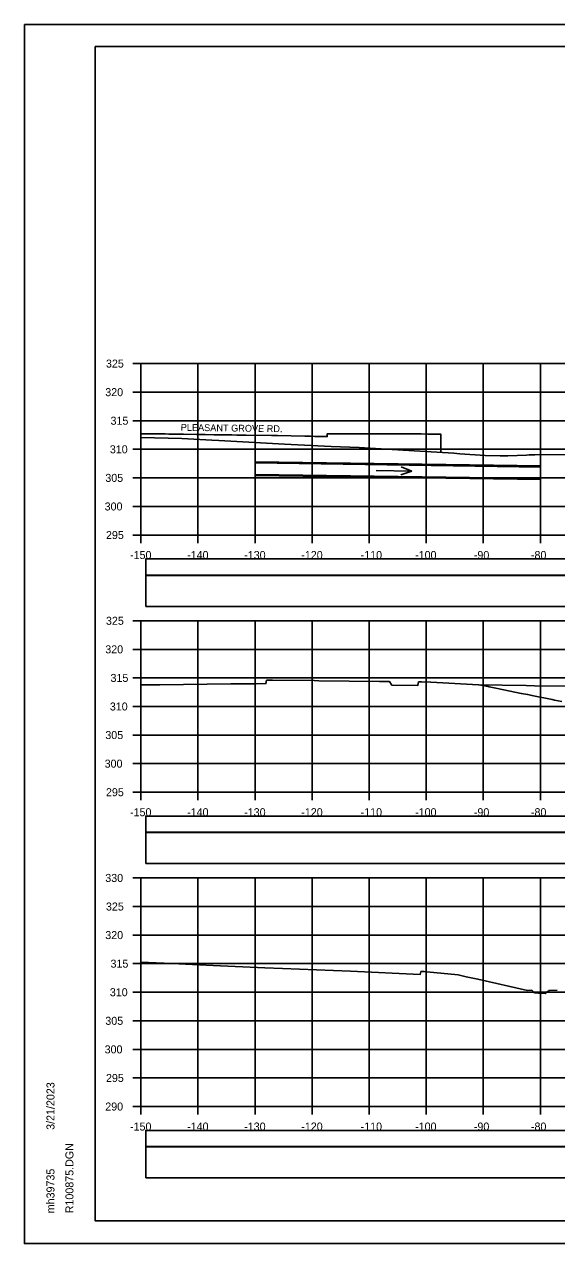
# Model space of a CAD drawing. Extents: x 1368122 to 1710785, y 373130 to 557566.
# Drawn here: x 1370518.5 to 1370611.8, y 373343.7 to 373557 of the extents above; entities that cross this region are included whole.
import ezdxf

# ---------------------------------------------------------------- set-up
doc = ezdxf.new("R2010")
doc.units = 0
for name, color, linetype in [('R_Axis', 7, 'Continuous'), ('R_Axis Annot', 7, 'Continuous'), ('R_Border', 7, 'Continuous'), ('R_Exist Surface', 7, 'Continuous'), ('R_Fin Surface', 7, 'Continuous'), ('R_Grid', 7, 'Continuous'), ('R_No Plot', 7, 'Continuous'), ('R_Water', 7, 'Continuous'), ('R_Water Annot', 7, 'Continuous')]:
    doc.layers.add(name, color=color, linetype=linetype)

msp = doc.modelspace()

# ---------------------------------------------------------------- linework, layer by layer
for points in [[(1370539.77, 373460.64), (1370838.07, 373460.64), (1370838.07, 373463.46), (1370539.77, 373463.46)], [(1370539.77, 373455.17), (1370838.07, 373455.17), (1370838.07, 373460.58), (1370539.77, 373460.58)], [(1370539.77, 373415.64), (1370838.07, 373415.64), (1370838.07, 373418.46), (1370539.77, 373418.46)], [(1370539.77, 373410.17), (1370838.07, 373410.17), (1370838.07, 373415.58), (1370539.77, 373415.58)], [(1370539.77, 373360.64), (1370838.07, 373360.64), (1370838.07, 373363.46), (1370539.77, 373363.46)], [(1370539.77, 373355.17), (1370838.07, 373355.17), (1370838.07, 373360.58), (1370539.77, 373360.58)]]:
    msp.add_lwpolyline(points, close=True)
at = {"layer": 'R_Axis'}
for p, q in [((1370537.52, 373497.65), (1370538.92, 373497.65)), ((1370538.92, 373467.65), (1370538.92, 373497.65)), ((1370537.52, 373492.65), (1370538.92, 373492.65)), ((1370537.52, 373487.65), (1370538.92, 373487.65)), ((1370537.52, 373482.65), (1370538.92, 373482.65)), ((1370537.52, 373477.65), (1370538.92, 373477.65)), ((1370537.52, 373472.65), (1370538.92, 373472.65)), ((1370537.52, 373467.65), (1370538.92, 373467.65)), ((1370538.92, 373467.65), (1370838.92, 373467.65)), ((1370538.92, 373466.25), (1370538.92, 373467.65)), ((1370548.92, 373466.25), (1370548.92, 373467.65)), ((1370558.92, 373466.25), (1370558.92, 373467.65)), ((1370568.92, 373466.25), (1370568.92, 373467.65)), ((1370578.92, 373466.25), (1370578.92, 373467.65)), ((1370588.92, 373466.25), (1370588.92, 373467.65)), ((1370598.92, 373466.25), (1370598.92, 373467.65)), ((1370608.92, 373466.25), (1370608.92, 373467.65)), ((1370537.52, 373452.65), (1370538.92, 373452.65)), ((1370538.92, 373422.65), (1370538.92, 373452.65)), ((1370537.52, 373447.65), (1370538.92, 373447.65)), ((1370537.52, 373442.65), (1370538.92, 373442.65)), ((1370537.52, 373437.65), (1370538.92, 373437.65)), ((1370537.52, 373432.65), (1370538.92, 373432.65)), ((1370537.52, 373427.65), (1370538.92, 373427.65)), ((1370537.52, 373422.65), (1370538.92, 373422.65)), ((1370538.92, 373422.65), (1370838.92, 373422.65)), ((1370538.92, 373421.25), (1370538.92, 373422.65)), ((1370548.92, 373421.25), (1370548.92, 373422.65)), ((1370558.92, 373421.25), (1370558.92, 373422.65)), ((1370568.92, 373421.25), (1370568.92, 373422.65)), ((1370578.92, 373421.25), (1370578.92, 373422.65)), ((1370588.92, 373421.25), (1370588.92, 373422.65)), ((1370598.92, 373421.25), (1370598.92, 373422.65)), ((1370608.92, 373421.25), (1370608.92, 373422.65)), ((1370537.52, 373407.65), (1370538.92, 373407.65)), ((1370538.92, 373367.65), (1370538.92, 373407.65)), ((1370537.52, 373402.65), (1370538.92, 373402.65)), ((1370537.52, 373397.65), (1370538.92, 373397.65)), ((1370537.52, 373392.65), (1370538.92, 373392.65)), ((1370537.52, 373387.65), (1370538.92, 373387.65)), ((1370537.52, 373382.65), (1370538.92, 373382.65)), ((1370537.52, 373377.65), (1370538.92, 373377.65)), ((1370537.52, 373372.65), (1370538.92, 373372.65)), ((1370537.52, 373367.65), (1370538.92, 373367.65)), ((1370538.92, 373367.65), (1370838.92, 373367.65)), ((1370538.92, 373366.25), (1370538.92, 373367.65)), ((1370548.92, 373366.25), (1370548.92, 373367.65)), ((1370558.92, 373366.25), (1370558.92, 373367.65)), ((1370568.92, 373366.25), (1370568.92, 373367.65)), ((1370578.92, 373366.25), (1370578.92, 373367.65)), ((1370588.92, 373366.25), (1370588.92, 373367.65)), ((1370598.92, 373366.25), (1370598.92, 373367.65)), ((1370608.92, 373366.25), (1370608.92, 373367.65))]:
    msp.add_line(p, q, dxfattribs=at)
at = {"layer": 'R_Border'}
for p, q in [((1370530.92, 373553.11), (1370847.1, 373553.11)), ((1370530.92, 373347.65), (1370530.92, 373553.11)), ((1370530.92, 373347.65), (1370530.92, 373347.65)), ((1370847.1, 373347.65), (1370530.92, 373347.65))]:
    msp.add_line(p, q, dxfattribs=at)
at = {"layer": 'R_Exist Surface'}
for points in [[(1370538.92, 373484.71), (1370546.1, 373484.52), (1370551.33, 373484.27), (1370552.56, 373484.18), (1370564.1, 373483.56), (1370572.25, 373483.14), (1370577.16, 373482.98), (1370586.78, 373482.39), (1370593.76, 373481.95), (1370594.25, 373481.93), (1370594.79, 373481.86), (1370599.26, 373481.56), (1370601.86, 373481.5), (1370603.23, 373481.5), (1370606.49, 373481.61), (1370606.96, 373481.68), (1370607.26, 373481.68), (1370607.93, 373481.68), (1370618, 373481.75)], [(1370538.92, 373441.46), (1370542.27, 373441.45), (1370554.68, 373441.64), (1370559.1, 373441.62), (1370560.82, 373441.65), (1370560.93, 373442.24), (1370560.94, 373442.25), (1370561.05, 373442.25), (1370561.86, 373442.25), (1370561.96, 373442.25), (1370569.28, 373442.18), (1370570.08, 373442.16), (1370580.75, 373442.03), (1370581.97, 373442.01), (1370582.51, 373442.01), (1370582.78, 373441.56), (1370582.87, 373441.4), (1370587.46, 373441.35), (1370587.47, 373441.39), (1370587.57, 373441.94), (1370587.62, 373441.94), (1370588.09, 373441.94), (1370589.72, 373441.9), (1370598.08, 373441.43), (1370606.43, 373441.3), (1370607.91, 373441.27), (1370614.82, 373441.18)], [(1370538.92, 373392.94), (1370544.33, 373392.68), (1370551.59, 373392.34), (1370560.65, 373391.92), (1370563.75, 373391.78), (1370575.65, 373391.32), (1370587.87, 373390.76), (1370587.99, 373391.23), (1370587.99, 373391.26), (1370588.56, 373391.25), (1370588.58, 373391.25), (1370589, 373391.21), (1370594.51, 373390.7), (1370595.9, 373390.37), (1370597.97, 373389.94), (1370606.68, 373387.98), (1370607.4, 373388.02), (1370607.84, 373387.62), (1370607.96, 373387.52), (1370608.6, 373387.48), (1370609.73, 373387.44), (1370610.13, 373387.72), (1370610.45, 373387.94), (1370611.84, 373388)]]:
    msp.add_lwpolyline(points, dxfattribs=at)
at = {"layer": 'R_Fin Surface'}
for points in [[(1370538.92, 373485.38), (1370541.3, 373485.35), (1370543.21, 373485.33), (1370543.83, 373485.32), (1370544.37, 373485.31), (1370546.41, 373485.28), (1370548.66, 373485.25), (1370549.28, 373485.24), (1370550.17, 373485.23), (1370551.7, 373485.21), (1370554.43, 373485.17), (1370554.78, 373485.17), (1370554.88, 373485.16), (1370555.71, 373485.15), (1370555.72, 373485.15), (1370555.97, 373485.15), (1370556.01, 373485.15), (1370557.39, 373485.12), (1370561.8, 373485.05), (1370561.85, 373485.05), (1370562.17, 373485.05), (1370562.87, 373485.04), (1370567.65, 373484.95), (1370567.68, 373484.95), (1370568.56, 373484.94), (1370568.63, 373484.94), (1370569.38, 373484.92), (1370570.65, 373484.9), (1370571.58, 373484.88), (1370571.58, 373485.08), (1370571.58, 373485.38), (1370571.94, 373485.38), (1370572.69, 373485.37), (1370573.16, 373485.37), (1370573.52, 373485.37), (1370574.59, 373485.37), (1370575.03, 373485.37), (1370576.66, 373485.36), (1370579.14, 373485.36), (1370579.14, 373485.36), (1370579.29, 373485.36), (1370579.39, 373485.36), (1370579.4, 373485.36), (1370580.9, 373485.35), (1370581.16, 373485.35), (1370583.65, 373485.35), (1370585.29, 373485.34), (1370586.28, 373485.34), (1370588.04, 373485.33), (1370589.18, 373485.32), (1370589.3, 373485.32), (1370589.41, 373485.32), (1370589.41, 373485.32), (1370589.64, 373485.32), (1370589.65, 373485.32), (1370589.68, 373485.32), (1370590.05, 373485.32), (1370590.34, 373485.31), (1370590.52, 373485.31), (1370590.54, 373485.31), (1370590.58, 373485.31), (1370590.65, 373485.31), (1370590.74, 373485.31), (1370591.49, 373485.29), (1370591.5, 373482.8), (1370591.5, 373482.09)], [(1370598.11, 373441.45), (1370599.75, 373441.12), (1370599.93, 373441.09), (1370601.13, 373440.84), (1370602.53, 373440.56), (1370605.57, 373439.95), (1370606.71, 373439.72), (1370607.43, 373439.58), (1370610.97, 373438.86), (1370611.41, 373438.77), (1370612.66, 373438.52)]]:
    msp.add_lwpolyline(points, dxfattribs=at)
at = {"layer": 'R_Grid'}
for p, q in [((1370538.92, 373497.65), (1370838.92, 373497.65)), ((1370538.92, 373467.65), (1370538.92, 373497.65)), ((1370548.92, 373467.65), (1370548.92, 373497.65)), ((1370558.92, 373467.65), (1370558.92, 373497.65)), ((1370568.92, 373467.65), (1370568.92, 373497.65)), ((1370578.92, 373467.65), (1370578.92, 373497.65)), ((1370588.92, 373467.65), (1370588.92, 373497.65)), ((1370598.92, 373467.65), (1370598.92, 373497.65)), ((1370608.92, 373467.65), (1370608.92, 373497.65)), ((1370538.92, 373492.65), (1370838.92, 373492.65)), ((1370538.92, 373487.65), (1370838.92, 373487.65)), ((1370538.92, 373482.65), (1370838.92, 373482.65)), ((1370538.92, 373477.65), (1370838.92, 373477.65)), ((1370538.92, 373472.65), (1370838.92, 373472.65)), ((1370538.92, 373467.65), (1370838.92, 373467.65)), ((1370538.92, 373452.65), (1370838.92, 373452.65)), ((1370538.92, 373422.65), (1370538.92, 373452.65)), ((1370548.92, 373422.65), (1370548.92, 373452.65)), ((1370558.92, 373422.65), (1370558.92, 373452.65)), ((1370568.92, 373422.65), (1370568.92, 373452.65)), ((1370578.92, 373422.65), (1370578.92, 373452.65)), ((1370588.92, 373422.65), (1370588.92, 373452.65)), ((1370598.92, 373422.65), (1370598.92, 373452.65)), ((1370608.92, 373422.65), (1370608.92, 373452.65)), ((1370538.92, 373447.65), (1370838.92, 373447.65)), ((1370538.92, 373442.65), (1370838.92, 373442.65)), ((1370538.92, 373437.65), (1370838.92, 373437.65)), ((1370538.92, 373432.65), (1370838.92, 373432.65)), ((1370538.92, 373427.65), (1370838.92, 373427.65)), ((1370538.92, 373422.65), (1370838.92, 373422.65)), ((1370538.92, 373407.65), (1370838.92, 373407.65)), ((1370538.92, 373367.65), (1370538.92, 373407.65)), ((1370548.92, 373367.65), (1370548.92, 373407.65)), ((1370558.92, 373367.65), (1370558.92, 373407.65)), ((1370568.92, 373367.65), (1370568.92, 373407.65)), ((1370578.92, 373367.65), (1370578.92, 373407.65)), ((1370588.92, 373367.65), (1370588.92, 373407.65)), ((1370598.92, 373367.65), (1370598.92, 373407.65)), ((1370608.92, 373367.65), (1370608.92, 373407.65)), ((1370538.92, 373402.65), (1370838.92, 373402.65)), ((1370538.92, 373397.65), (1370838.92, 373397.65)), ((1370538.92, 373392.65), (1370838.92, 373392.65)), ((1370538.92, 373387.65), (1370838.92, 373387.65)), ((1370538.92, 373382.65), (1370838.92, 373382.65)), ((1370538.92, 373377.65), (1370838.92, 373377.65)), ((1370538.92, 373372.65), (1370838.92, 373372.65)), ((1370538.92, 373367.65), (1370838.92, 373367.65))]:
    msp.add_line(p, q, dxfattribs=at)
at = {"layer": 'R_No Plot'}
for p, q in [((1370518.52, 373557), (1370851.85, 373557)), ((1370558.97, 373480.48), (1370609.07, 373479.76)), ((1370558.97, 373478.06), (1370609.07, 373477.34)), ((1370518.52, 373343.67), (1370851.85, 373343.67))]:
    msp.add_line(p, q, dxfattribs=at)
for points in [[(1370518.51, 373557), (1370851.85, 373557), (1370851.85, 373343.66), (1370518.51, 373343.66)], [(1370764.84, 373553.11), (1370784.46, 373553.11), (1370784.46, 373543.23), (1370800.57, 373543.23), (1370823.77, 373543.23), (1370823.89, 373515.07), (1370847.1, 373515.07), (1370847.1, 373347.65), (1370530.92, 373347.65), (1370530.92, 373553.11)]]:
    msp.add_lwpolyline(points, close=True, dxfattribs=at)
at = {"layer": 'R_Water'}
for p, q in [((1370558.97, 373480.27), (1370609.07, 373479.55)), ((1370558.97, 373478.27), (1370609.07, 373477.55))]:
    msp.add_line(p, q, dxfattribs=at)
at = {"layer": 'R_Water Annot'}
for p, q in [((1370586.42, 373478.84), (1370584.51, 373479.56)), ((1370580.14, 373478.93), (1370586.42, 373478.84)), ((1370586.42, 373478.84), (1370584.49, 373478.16))]:
    msp.add_line(p, q, dxfattribs=at)

# ---------------------------------------------------------------- texts
at = {"layer": 'R_Axis Annot'}
for s, p in [('325', (1370532.81, 373496.95)), ('320', (1370532.69, 373491.95)), ('315', (1370533.61, 373486.95)), ('310', (1370533.49, 373481.95)), ('305', (1370532.7, 373476.95)), ('300', (1370532.58, 373471.95)), ('295', (1370532.81, 373466.95)), ('-150', (1370537.03, 373463.45)), ('-140', (1370547.03, 373463.45)), ('-130', (1370557.03, 373463.45)), ('-120', (1370567.03, 373463.45)), ('-110', (1370577.43, 373463.45)), ('-100', (1370586.97, 373463.45)), ('-90', (1370597.26, 373463.45)), ('-80', (1370607.26, 373463.45)), ('325', (1370532.81, 373451.95)), ('320', (1370532.69, 373446.95)), ('315', (1370533.61, 373441.95)), ('310', (1370533.49, 373436.95)), ('305', (1370532.7, 373431.95)), ('300', (1370532.58, 373426.95)), ('295', (1370532.81, 373421.95)), ('-150', (1370537.03, 373418.45)), ('-140', (1370547.03, 373418.45)), ('-130', (1370557.03, 373418.45)), ('-120', (1370567.03, 373418.45)), ('-110', (1370577.43, 373418.45)), ('-100', (1370586.97, 373418.45)), ('-90', (1370597.26, 373418.45)), ('-80', (1370607.26, 373418.45)), ('330', (1370532.69, 373406.95)), ('325', (1370532.81, 373401.95)), ('320', (1370532.69, 373396.95)), ('315', (1370533.61, 373391.95)), ('310', (1370533.49, 373386.95)), ('305', (1370532.7, 373381.95)), ('300', (1370532.58, 373376.95)), ('295', (1370532.81, 373371.95)), ('290', (1370532.69, 373366.95)), ('-150', (1370537.03, 373363.45)), ('-140', (1370547.03, 373363.45)), ('-130', (1370557.03, 373363.45)), ('-120', (1370567.03, 373363.45)), ('-110', (1370577.43, 373363.45)), ('-100', (1370586.97, 373363.45)), ('-90', (1370597.26, 373363.45)), ('-80', (1370607.26, 373363.45))]:
    msp.add_text(s, height=1.4, dxfattribs=at).set_placement(p)
at = {"layer": 'R_Border'}
for s, p in [('3/21/2023', (1370523.79, 373363.57)), ('R100875.DGN', (1370527.11, 373348.97)), ('mh39735', (1370523.79, 373348.97))]:
    msp.add_text(s, height=1.4, rotation=90, dxfattribs=at).set_placement(p)
at = {"layer": 'R_Fin Surface'}
msp.add_text('PLEASANT GROVE RD.', height=1.2, rotation=359.158, dxfattribs=at).set_placement((1370545.9, 373485.9))

doc.saveas('drawing.dxf')
